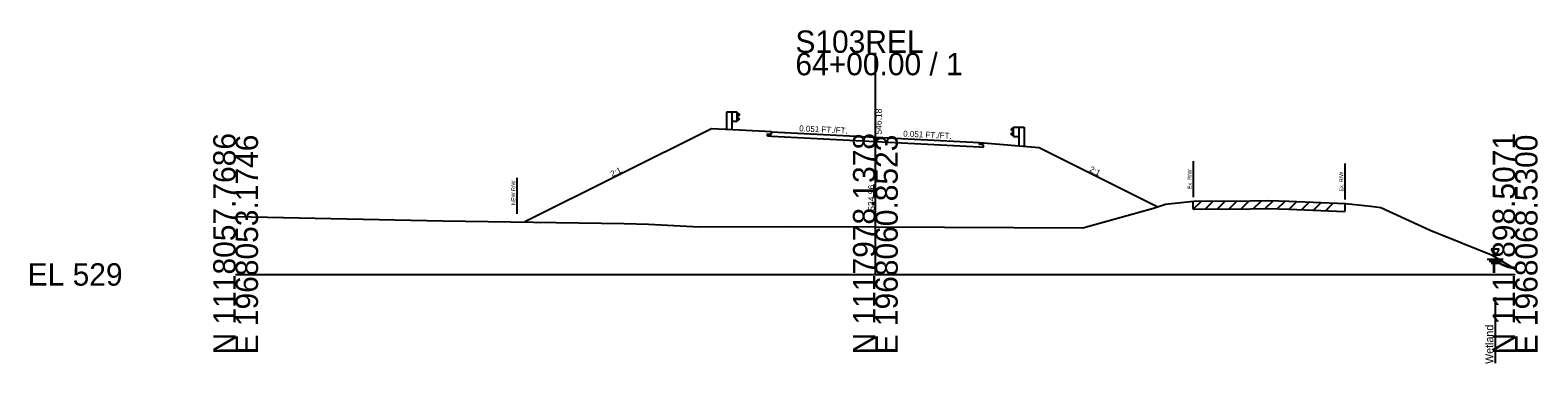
# Model space of a CAD drawing. Extents: x -26 to 163, y -10 to 45020.
# Drawn here: x -25.7 to 162.8, y 21988.8 to 22030.6 of the extents above; entities that cross this region are included whole.
import ezdxf

# ---------------------------------------------------------------- set-up
doc = ezdxf.new("R2010")
doc.units = 0
for name, color, linetype in [('RD_GPK_XS_Cell', 7, 'Continuous'), ('RD_XS_Base', 7, 'Continuous'), ('RD_XS_EarthShd', 7, 'Continuous'), ('RD_XS_ExGround', 7, 'Continuous'), ('RD_XS_ExPaveRet', 7, 'Continuous'), ('RD_XS_ExRW', 7, 'Continuous'), ('RD_XS_EXWetland', 7, 'Continuous'), ('RD_XS_GR', 7, 'Continuous'), ('RD_XS_NewRW', 7, 'Continuous'), ('RD_XS_Pave', 7, 'Continuous'), ('RD_XS_PaveOvlay', 7, 'Continuous'), ('RD_XS_TieSlope', 7, 'Continuous'), ('RD_XS_TX_Elev_EX', 7, 'Continuous'), ('RD_XS_TX_Elev_PR', 7, 'Continuous'), ('RD_XS_TX_Slope', 7, 'Continuous')]:
    doc.layers.add(name, color=color, linetype=linetype)

msp = doc.modelspace()

# ---------------------------------------------------------------- linework, layer by layer
at = {"layer": 'RD_GPK_XS_Cell'}
for p, q in [((80, 22000), (80, 22027.71)), ((0, 22000), (80, 22000)), ((80, 22000), (160, 22000))]:
    msp.add_line(p, q, dxfattribs=at)
at = {"layer": 'RD_XS_Base'}
for p, q in [((67, 22017.28), (80, 22016.62)), ((80, 22016.62), (93, 22015.95))]:
    msp.add_line(p, q, dxfattribs=at)
at = {"layer": 'RD_XS_EarthShd'}
for p, q in [((63, 22018.05), (59.5, 22018.23)), ((67, 22017.84), (63, 22018.05)), ((93, 22016.51), (100.5, 22015.88))]:
    msp.add_line(p, q, dxfattribs=at)
at = {"layer": 'RD_XS_ExGround'}
for p, q in [((105.93, 22005.83), (114.76, 22008.28)), ((114.76, 22008.28), (116.28, 22008.79)), ((116.28, 22008.79), (117.04, 22008.86)), ((117.04, 22008.86), (119.83, 22009.17)), ((119.83, 22009.17), (126.88, 22009.2)), ((126.88, 22009.2), (129.2, 22009.24)), ((129.2, 22009.24), (131.72, 22009.16)), ((131.72, 22009.16), (138.79, 22008.86)), ((138.79, 22008.86), (141.95, 22008.55)), ((141.95, 22008.55), (143.2, 22008.39)), ((143.2, 22008.39), (149.39, 22005.54)), ((0, 22007.26), (25.91, 22006.72)), ((25.91, 22006.72), (48.6, 22006.38)), ((48.6, 22006.38), (51.63, 22006.29)), ((51.63, 22006.29), (57.98, 22005.97)), ((57.98, 22005.97), (69.37, 22006.01)), ((69.37, 22006.01), (80, 22005.96)), ((80, 22005.96), (105.93, 22005.83)), ((149.39, 22005.54), (157.03, 22002.47)), ((157.03, 22002.47), (160, 22000.65))]:
    msp.add_line(p, q, dxfattribs=at)
at = {"layer": 'RD_XS_ExPaveRet'}
for p, q in [((119.74, 22008.16), (120.76, 22009.17)), ((119.74, 22008.16), (119.74, 22009.16)), ((119.74, 22008.16), (119.83, 22008.17)), ((119.83, 22008.17), (126.88, 22008.2)), ((121.24, 22008.17), (122.25, 22009.18)), ((122.75, 22008.18), (123.75, 22009.18)), ((124.25, 22008.19), (125.25, 22009.19)), ((125.75, 22008.19), (126.76, 22009.2)), ((126.88, 22008.2), (129.2, 22008.24)), ((127.25, 22008.2), (128.27, 22009.22)), ((128.76, 22008.23), (129.75, 22009.22)), ((129.2, 22008.24), (131.72, 22008.16)), ((130.26, 22008.2), (131.23, 22009.17)), ((131.72, 22008.16), (138.69, 22007.86)), ((131.76, 22008.15), (132.72, 22009.11)), ((133.27, 22008.09), (134.23, 22009.05)), ((134.77, 22008.03), (135.73, 22008.99)), ((136.27, 22007.96), (137.23, 22008.92)), ((138.69, 22008.86), (138.69, 22007.86))]:
    msp.add_line(p, q, dxfattribs=at)
at = {"layer": 'RD_XS_ExRW'}
for p, q in [((119.74, 22014.16), (119.74, 22009.66)), ((138.69, 22013.86), (138.69, 22009.36))]:
    msp.add_line(p, q, dxfattribs=at)
at = {"layer": 'RD_XS_EXWetland'}
for p, q in [((156.52, 22001.92), (158.52, 22001.92)), ((157.02, 22003.17), (157.52, 22002.17)), ((158.02, 22003.17), (157.02, 22003.17)), ((157.52, 22002.17), (158.02, 22003.17)), ((156.77, 22001.67), (158.27, 22001.67)), ((157.02, 22001.42), (158.02, 22001.42)), ((157.52, 21997.17), (157.52, 21988.92))]:
    msp.add_line(p, q, dxfattribs=at)
at = {"layer": 'RD_XS_GR'}
for p, q in [((62.06, 22020.3), (61.4, 22020.3)), ((61.4, 22020.3), (61.4, 22018.13)), ((62.06, 22020.3), (61.4, 22020.3)), ((62.73, 22020.3), (62.06, 22020.3)), ((62.73, 22020.3), (62.06, 22020.3)), ((62.06, 22020.3), (62.06, 22018.1)), ((62.73, 22019.13), (62.06, 22019.13)), ((62.73, 22019.13), (62.06, 22019.13)), ((62.73, 22019.13), (62.73, 22020.3)), ((62.73, 22019.13), (62.73, 22020.3)), ((62.73, 22020.22), (63, 22020.02)), ((62.73, 22020.22), (63, 22020.02)), ((63, 22019.97), (62.73, 22019.77)), ((63, 22019.97), (62.73, 22019.77)), ((63, 22019.45), (62.73, 22019.65)), ((63, 22019.45), (62.73, 22019.65)), ((62.73, 22019.2), (63, 22019.4)), ((62.73, 22019.2), (63, 22019.4)), ((63, 22020.02), (63, 22019.97)), ((63, 22020.02), (63, 22019.97)), ((63, 22019.4), (63, 22019.45)), ((63, 22019.4), (63, 22019.45)), ((97.27, 22018.35), (97, 22018.15)), ((97, 22018.15), (97, 22018.1)), ((97, 22018.1), (97.27, 22017.9)), ((97, 22017.58), (97.27, 22017.78)), ((97, 22017.53), (97, 22017.58)), ((97.27, 22017.33), (97, 22017.53)), ((97.27, 22017.26), (97.27, 22018.42)), ((97.27, 22018.42), (97.94, 22018.42)), ((97.27, 22017.26), (97.94, 22017.26)), ((97.94, 22018.42), (97.94, 22016.1)), ((97.94, 22018.42), (98.6, 22018.42)), ((98.6, 22018.42), (98.6, 22016.04))]:
    msp.add_line(p, q, dxfattribs=at)
at = {"layer": 'RD_XS_NewRW'}
msp.add_line((35.18, 22012.08), (35.18, 22007.58), dxfattribs=at)
at = {"layer": 'RD_XS_Pave'}
for p, q in [((66.5, 22017.59), (67, 22017.56)), ((66.5, 22017.31), (66.5, 22017.59)), ((67, 22017.28), (66.5, 22017.31)), ((67, 22017.56), (67, 22017.84)), ((93, 22016.23), (93, 22016.51)), ((93.5, 22016.2), (93, 22016.23)), ((93, 22015.95), (93.5, 22015.92)), ((93.5, 22015.92), (93.5, 22016.2))]:
    msp.add_line(p, q, dxfattribs=at)
at = {"layer": 'RD_XS_PaveOvlay'}
for p, q in [((67, 22017.84), (80, 22017.18)), ((80, 22017.18), (93, 22016.51))]:
    msp.add_line(p, q, dxfattribs=at)
at = {"layer": 'RD_XS_TieSlope'}
for p, q in [((59.5, 22018.23), (36.18, 22006.57)), ((100.5, 22015.88), (115.33, 22008.47))]:
    msp.add_line(p, q, dxfattribs=at)

# ---------------------------------------------------------------- texts
at = {"layer": 'RD_GPK_XS_Cell'}
for s, p in [('S103REL', (70, 22027.71)), ('64+00.00 / 1', (70, 22024.91)), ('EL 529', (-26, 21998.6))]:
    msp.add_text(s, height=2.8, dxfattribs=at).set_placement(p)
for s, p in [('N 1118057.7686', (0, 21990)), ('E 1968053.1746', (2.8, 21990)), ('N 1117978.1378', (80, 21990)), ('E 1968060.8523', (82.8, 21990)), ('N 1117898.5071', (160, 21990)), ('E 1968068.5300', (162.8, 21990))]:
    msp.add_text(s, height=2.8, rotation=90, dxfattribs=at).set_placement(p)
at = {"layer": 'RD_XS_ExRW'}
for p in [(119.55, 22010.66), (138.5, 22010.37)]:
    msp.add_text('Ex. R/W ', height=0.488, rotation=90, dxfattribs=at).set_placement(p)
at = {"layer": 'RD_XS_EXWetland'}
msp.add_text('Wetland ', height=1, rotation=90, dxfattribs=at).set_placement((157.27, 21988.81))
at = {"layer": 'RD_XS_NewRW'}
msp.add_text('NEW R/W ', height=0.488, rotation=90, dxfattribs=at).set_placement((34.98, 22008.68))
at = {"layer": 'RD_XS_TX_Elev_EX'}
msp.add_text('534.96', height=0.8, rotation=90, dxfattribs=at).set_placement((79.9, 22007.96))
at = {"layer": 'RD_XS_TX_Elev_PR'}
msp.add_text(' 546.18', height=0.8, rotation=90, dxfattribs=at).set_placement((80.8, 22017.18))
at = {"layer": 'RD_XS_TX_Slope'}
for s, rotation, p in [('0.051 FT./FT.', 357.0633, (70.46, 22017.91)), ('0.051 FT./FT.', 357.0633, (83.46, 22017.25)), ('2:1', 26.5651, (47.09, 22012.17)), ('2:1', 333.4349, (106.68, 22012.92))]:
    msp.add_text(s, height=0.75, rotation=rotation, dxfattribs=at).set_placement(p)

doc.saveas('drawing.dxf')
